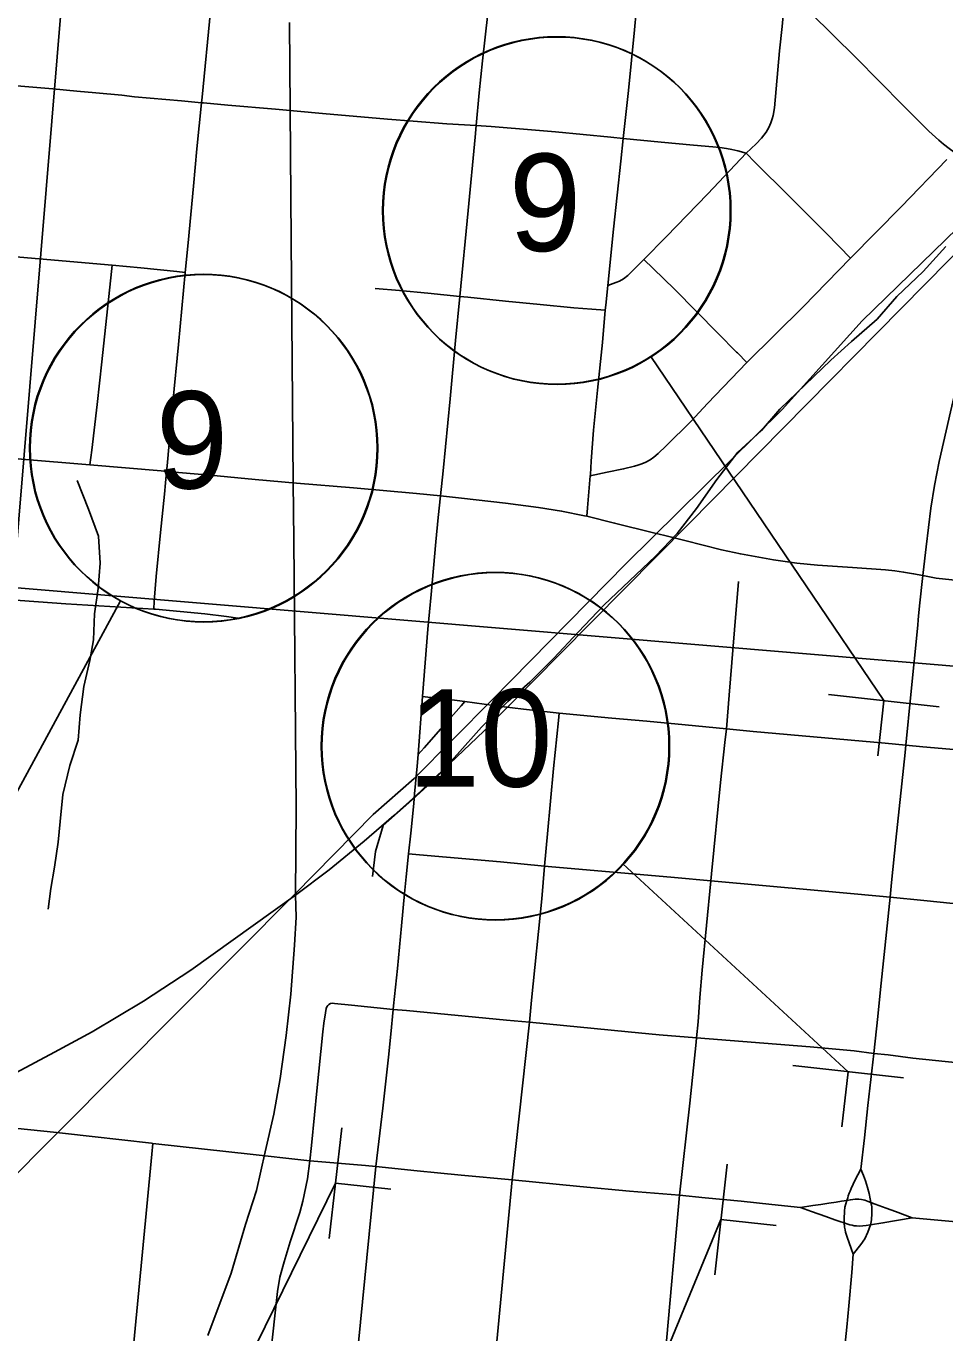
# Model space of a CAD drawing. Extents: x 0 to 1067, y 0 to 440.
# Drawn here: x 348.64 to 375.06, y 98.13 to 135.74 of the extents above; entities that cross this region are included whole.
import ezdxf

# ---------------------------------------------------------------- set-up
doc = ezdxf.new("R2010")
doc.units = 0
for name, color, linetype in [('Default', 7, 'Continuous'), ('GM_X_City_Street', 7, 'Continuous'), ('GM_X_Minor_River', 7, 'Continuous'), ('GM_X_Rail_Line', 7, 'Continuous'), ('GM_X_Section', 7, 'Continuous'), ('GM_X_State_Route', 7, 'Continuous'), ('GM_X_US_Route', 7, 'Continuous'), ('SH_Masking', 7, 'Continuous'), ('SH_Text', 7, 'Continuous'), ('SN_P_Signs', 7, 'Continuous')]:
    doc.layers.add(name, color=color, linetype=linetype)

msp = doc.modelspace()

# ---------------------------------------------------------------- linework, layer by layer
at = {"layer": 'Default'}
msp.add_line((358.398, 102.942), (356.8, 103.085), dxfattribs=at)
for points in [[(376.116, 128.559), (375.98, 127.967), (375.728, 126.841), (375.5, 125.823), (375.228, 124.636), (374.902, 123.209), (374.764, 122.519), (374.657, 121.861), (374.521, 120.755), (374.438, 120.015), (374.428, 119.923), (374.336, 119.054)], [(374.336, 119.054), (374.307, 118.759), (374.296, 118.648), (374.282, 118.501), (374.089, 116.5), (373.937, 115.042), (373.918, 114.831), (373.652, 112.312), (373.531, 111.088), (373.488, 110.667), (373.216, 108.012), (373.139, 107.235), (373.023, 106.172), (372.852, 104.672), (372.749, 103.747), (372.647, 102.84)], [(349.421, 103.902), (346.994, 104.157), (346.241, 104.236)], [(352.283, 103.581), (352.243, 103.585), (349.688, 103.874), (349.421, 103.902)], [(356.8, 103.085), (356.542, 103.11), (355.169, 103.261), (352.283, 103.581)], [(362.618, 102.534), (361.155, 102.668), (360.472, 102.733), (359.881, 102.788), (358.694, 102.915)], [(372.647, 102.84), (372.563, 102.676), (372.488, 102.534), (372.428, 102.408), (372.367, 102.28), (372.338, 102.211), (372.313, 102.146), (372.286, 102.069), (372.268, 102.013), (372.246, 101.937)], [(372.924, 101.242), (372.94, 101.325), (372.949, 101.39), (372.966, 101.555), (372.965, 101.679), (372.961, 101.751), (372.949, 101.817), (372.936, 101.882), (372.916, 101.986), (372.882, 102.138), (372.834, 102.316), (372.776, 102.507), (372.723, 102.658), (372.647, 102.84)], [(367.429, 102.089), (365.994, 102.212), (364.562, 102.339), (362.618, 102.534)], [(370.909, 101.738), (370.087, 101.824), (369.204, 101.916), (368.17, 102.019), (367.429, 102.089)], [(372.246, 101.937), (372.09, 101.916), (371.933, 101.894), (371.728, 101.863), (371.497, 101.826), (371.265, 101.791), (370.909, 101.738)], [(370.909, 101.738), (371.231, 101.619), (371.638, 101.479), (371.903, 101.383), (372.047, 101.335), (372.167, 101.296)], [(372.167, 101.296), (372.24, 101.267), (372.331, 101.24), (372.393, 101.225), (372.453, 101.213), (372.522, 101.206)], [(372.522, 101.206), (372.612, 101.204), (372.702, 101.21), (372.798, 101.222), (372.924, 101.242)]]:
    msp.add_lwpolyline(points, dxfattribs=at)
at = {"layer": 'GM_X_City_Street'}
for p, q in [((362.618, 102.534), (363.112, 107.076)), ((362.175, 97.883), (362.618, 102.534))]:
    msp.add_line(p, q, dxfattribs=at)
for points in [[(352.306, 118.96), (352.323, 119.189), (352.375, 119.899), (352.503, 121.16), (352.618, 122.271), (352.678, 122.924), (352.693, 123.087), (352.853, 124.905), (353.016, 126.572), (353.117, 127.608), (353.216, 128.647), (353.298, 129.499), (353.449, 131.13), (353.546, 132.206), (353.686, 133.531), (353.703, 133.689), (353.938, 136.172), (354.068, 137.506), (354.09, 137.748), (354.253, 139.547), (354.355, 140.548), (354.416, 141.332), (354.441, 141.657)], [(364.764, 121.631), (364.785, 121.875), (364.865, 122.791), (364.869, 122.831), (364.89, 123.218), (364.96, 124.109), (365.071, 125.258), (365.212, 126.629), (365.296, 127.562), (365.309, 127.705), (365.367, 128.272), (365.533, 129.889), (365.743, 131.849), (365.813, 132.503), (365.963, 133.886), (366.133, 135.626), (366.236, 136.674), (366.354, 137.865), (366.457, 138.781), (366.632, 140.525), (366.659, 140.791)], [(369.35, 132.081), (369.636, 132.347), (369.786, 132.513), (369.923, 132.69), (370, 132.818), (370.06, 132.954), (370.097, 133.068), (370.123, 133.167), (370.163, 133.387), (370.311, 135.022), (370.381, 135.727), (370.436, 136.263), (370.528, 137.175), (370.683, 138.884), (370.788, 140.109), (370.817, 140.452)], [(358.694, 102.915), (358.902, 104.593), (359.056, 106.065), (359.125, 106.727), (359.198, 107.44), (359.208, 107.542), (359.317, 108.619), (359.431, 109.844), (359.521, 110.77), (359.568, 111.252), (359.639, 111.913), (359.704, 112.512), (359.787, 113.366), (359.813, 113.642), (359.888, 114.443), (359.913, 114.772), (360.043, 116.447), (360.192, 118.381), (360.289, 119.379), (360.424, 120.896), (360.487, 121.6), (360.554, 122.217), (360.632, 122.935), (360.838, 125.014), (360.988, 126.685), (361.112, 127.956), (361.354, 130.432), (361.551, 132.545), (361.582, 132.878), (361.671, 133.819), (361.766, 134.739), (361.998, 136.788)], [(371.126, 136.188), (371.196, 136.121), (372.504, 134.831), (373.862, 133.451), (374.599, 132.716), (374.892, 132.451), (375.025, 132.34), (375.191, 132.212), (375.33, 132.111), (375.58, 131.985), (375.936, 131.818), (376.328, 131.671), (376.752, 131.513)], [(347.454, 134.094), (349.403, 133.93), (350.095, 133.865), (350.647, 133.819), (351.387, 133.747), (351.756, 133.706), (353.109, 133.584), (353.686, 133.531), (353.735, 133.526), (354.439, 133.46), (355.813, 133.349), (357.165, 133.221), (359.031, 133.058), (359.774, 132.998), (360.74, 132.929), (361.582, 132.878), (362.016, 132.851), (363.292, 132.741), (363.861, 132.692), (365.455, 132.538), (365.813, 132.503), (366.902, 132.4), (367.83, 132.312), (368.388, 132.264), (368.592, 132.241), (368.781, 132.212), (368.934, 132.183), (369.108, 132.146), (369.35, 132.081)], [(365.367, 128.272), (365.599, 128.359), (365.705, 128.401), (365.818, 128.465), (365.944, 128.561), (366.079, 128.69), (366.404, 129.021), (367.048, 129.676), (368.249, 130.906), (369.35, 132.081)], [(369.35, 132.081), (369.608, 131.811), (370.589, 130.842), (371.221, 130.211), (371.326, 130.106), (371.642, 129.791), (372.026, 129.391), (372.351, 129.062)], [(364.865, 122.791), (365.348, 122.896), (365.823, 122.993), (366.137, 123.073), (366.234, 123.104), (366.35, 123.144), (366.462, 123.186), (366.583, 123.256), (366.697, 123.331), (366.817, 123.433), (367.044, 123.654), (367.753, 124.356), (368.24, 124.881), (369.372, 126.058), (370.992, 127.658), (372.351, 129.062), (373.806, 130.536), (375.122, 131.902)], [(346.901, 129.218), (351.111, 128.853), (351.937, 128.782), (352.971, 128.672), (353.216, 128.647)], [(366.404, 129.021), (366.669, 128.765), (367.289, 128.169), (368.545, 126.892), (369.069, 126.357), (369.095, 126.33), (369.372, 126.058)], [(350.474, 123.111), (350.524, 123.534), (350.681, 124.845), (350.813, 126.072), (351.091, 128.672), (351.111, 128.853)], [(358.673, 128.187), (359.38, 128.124), (360.196, 128.048), (361.112, 127.956), (361.347, 127.932), (362.424, 127.825), (363.426, 127.721), (364.392, 127.63), (364.913, 127.591), (365.296, 127.562)], [(344.664, 123.625), (347.246, 123.396), (348.507, 123.277), (350.474, 123.111)], [(350.474, 123.111), (352.519, 122.938), (352.678, 122.924)], [(352.678, 122.924), (353.929, 122.812), (355.227, 122.691), (356.416, 122.585), (358.05, 122.45), (359.867, 122.289), (360.554, 122.217)], [(360.554, 122.217), (361.163, 122.153), (362.421, 122.012), (363.379, 121.886), (364.039, 121.779), (364.694, 121.648), (364.764, 121.631)], [(364.764, 121.631), (365.561, 121.435), (366.682, 121.158), (367.008, 121.077), (367.586, 120.932), (368.635, 120.667), (369.182, 120.548), (370.138, 120.381), (370.804, 120.284), (371.399, 120.222), (372.405, 120.154), (373.36, 120.09), (373.621, 120.065), (373.878, 120.026), (374.164, 119.976), (374.428, 119.923)], [(339.198, 120.018), (340.534, 119.899), (344.19, 119.569), (345.037, 119.494), (346.917, 119.328), (348.07, 119.234), (349.776, 119.115), (352.306, 118.96), (352.36, 118.957), (353.071, 118.894), (353.774, 118.823), (354.397, 118.748), (354.727, 118.699)], [(368.779, 115.515), (368.863, 116.482), (369.01, 118.358), (369.13, 119.752)], [(374.428, 119.923), (374.81, 119.853), (375.264, 119.799), (376.526, 119.675), (379.34, 119.399), (379.581, 119.368)], [(359.913, 114.772), (360.085, 114.967), (360.566, 115.513), (361.148, 116.176), (361.253, 116.296)], [(360.043, 116.447), (360.192, 116.429), (360.738, 116.366), (361.253, 116.296), (361.536, 116.259), (362.086, 116.184), (362.313, 116.153), (362.94, 116.077), (363.967, 115.963), (365.489, 115.818), (366.489, 115.734), (367.595, 115.628), (368.779, 115.515), (369.548, 115.441), (373.345, 115.101), (373.937, 115.042)], [(363.112, 107.076), (363.175, 107.703), (363.474, 110.62), (363.552, 111.561), (363.63, 112.496), (363.808, 114.37), (363.946, 115.749), (363.967, 115.963)], [(367.429, 102.089), (367.726, 104.742), (367.906, 106.493), (367.918, 106.617), (367.964, 107.082), (368.02, 107.785), (368.085, 108.564), (368.33, 111.143), (368.349, 111.34), (368.613, 113.968), (368.734, 115.12), (368.779, 115.515)], [(373.937, 115.042), (374.425, 114.997), (375.645, 114.889), (378.78, 114.612), (379.021, 114.591), (382.71, 114.268), (383.853, 114.166), (384.189, 114.124), (386.417, 113.917), (388.447, 113.728), (390.523, 113.524), (394.165, 113.168), (394.515, 113.136), (398.504, 112.778), (398.648, 112.765), (408.548, 111.817), (410.23, 111.667), (412.922, 111.384), (414.026, 111.268), (417.287, 110.919), (420.686, 110.598), (421.107, 110.558)], [(359.639, 111.913), (359.952, 111.886), (362.281, 111.687), (363.552, 111.561), (363.651, 111.551), (367.291, 111.239), (368.33, 111.143), (371.407, 110.857), (373.18, 110.695), (373.488, 110.667)], [(373.488, 110.667), (374.457, 110.569), (375.678, 110.446), (377.192, 110.311), (378.525, 110.185), (378.577, 110.18), (379.637, 110.085), (382.924, 109.793), (383.45, 109.743), (384.366, 109.656), (385.977, 109.501), (386.171, 109.475), (390.093, 109.102), (390.987, 109.016), (393.869, 108.743), (394.081, 108.724), (395.539, 108.593), (397.216, 108.45), (398.078, 108.377), (399.342, 108.265), (402.999, 107.914)], [(356.8, 103.085), (356.844, 103.524), (356.931, 104.407), (357.002, 105.095), (357.176, 106.789), (357.205, 107.041), (357.245, 107.343), (357.267, 107.464), (357.286, 107.514), (357.312, 107.555), (357.345, 107.584)], [(357.345, 107.584), (357.393, 107.606), (357.449, 107.614), (357.504, 107.61), (357.996, 107.558), (359.198, 107.44)], [(359.198, 107.44), (359.576, 107.403), (362.459, 107.13), (363.112, 107.076)], [(363.112, 107.076), (365.954, 106.794), (366.845, 106.707), (367.918, 106.617)], [(367.918, 106.617), (371.185, 106.358), (372.459, 106.251), (373.023, 106.172)], [(373.023, 106.172), (373.433, 106.128), (374.144, 106.037), (376.471, 105.8), (378.114, 105.635)], [(341.077, 85.173), (347.518, 91.121), (349.745, 93.08), (349.999, 93.346), (350.184, 93.574), (350.348, 93.817), (350.549, 94.171), (350.777, 94.637), (351.347, 96.011), (351.486, 96.432), (351.576, 96.791), (351.651, 97.19), (351.737, 97.854), (352.253, 103.274), (352.283, 103.581)], [(354.833, 88.561), (354.797, 88.851), (354.775, 89.023), (354.775, 89.152), (354.79, 89.3), (355.504, 95.991), (355.865, 99.321), (355.934, 99.736), (356.062, 100.17), (356.23, 100.752), (356.509, 101.598), (356.594, 101.922), (356.729, 102.563), (356.8, 103.085)], [(356.818, 83.639), (356.791, 83.69), (356.786, 83.779), (356.791, 83.892), (357.363, 89.368), (357.995, 95.811), (358.694, 102.915)], [(365.508, 82.695), (365.533, 82.923), (366.142, 88.583), (366.58, 92.902), (367.014, 97.469), (367.429, 102.089)]]:
    msp.add_lwpolyline(points, dxfattribs=at)
at = {"layer": 'GM_X_Minor_River'}
for points in [[(358.604, 111.259), (358.686, 111.987), (358.904, 112.735), (359.644, 113.384), (360.384, 114.055), (361.035, 114.773), (361.732, 115.558), (362.496, 116.297), (363.121, 116.856), (363.817, 117.551), (364.513, 118.291), (365.255, 119.076), (365.996, 119.77), (366.738, 120.486), (367.364, 121.136), (367.923, 121.856), (368.507, 122.689), (369.113, 123.476), (369.785, 124.103), (370.319, 124.709), (371.779, 126.12), (372.38, 126.656), (373.12, 127.305), (373.678, 127.956), (374.443, 128.672), (375.093, 129.39)], [(349.273, 110.324), (349.352, 110.915), (349.454, 111.528), (349.558, 112.256), (349.614, 112.847), (349.696, 113.621), (349.893, 114.46), (350.133, 115.185), (350.192, 115.913), (350.297, 116.732), (350.47, 117.481), (350.571, 118.072), (350.607, 118.823), (350.711, 119.55), (350.769, 120.278), (350.715, 121.054), (350.432, 121.833), (350.105, 122.659)]]:
    msp.add_lwpolyline(points, dxfattribs=at)
at = {"layer": 'GM_X_Rail_Line'}
for points in [[(353.862, 98.058), (354.532, 99.851), (354.947, 101.249), (355.26, 102.225), (355.509, 103.335), (355.758, 104.427), (355.943, 105.448), (356.115, 106.686), (356.249, 107.879), (356.358, 109.283), (356.402, 110.093), (356.384, 110.723), (356.404, 113.246), (356.341, 120.947), (356.322, 122.613), (356.264, 129.575), (356.216, 135.845)], [(348.344, 105.612), (349.451, 106.204), (350.534, 106.789), (352.017, 107.674), (353.373, 108.565), (356.384, 110.723), (357.351, 111.455), (358.357, 112.276), (359.217, 113.021), (359.847, 113.588), (361.8, 115.445), (363.987, 117.665), (367.695, 121.418), (376.531, 130.37), (377.357, 131.235), (377.909, 131.904), (378.756, 132.93)], [(356.37, 110.755), (358.619, 113.048), (359.795, 114.081), (362.038, 116.348), (365.9, 120.275), (370.388, 124.707), (372.687, 127.253), (375.425, 129.919), (376.58, 131.044)], [(356.37, 110.755), (341.091, 95.394), (330.427, 84.614)]]:
    msp.add_lwpolyline(points, dxfattribs=at)
at = {"layer": 'GM_X_Section'}
for points in [[(293.305, 184.745), (353.183, 178.942), (348.264, 119.585), (289.359, 125.481)], [(353.183, 178.942), (415.565, 173.729), (410.18, 114.397), (348.264, 119.585)], [(410.18, 114.397), (404.583, 52.958), (342.16, 58.91), (348.264, 119.585)]]:
    msp.add_lwpolyline(points, close=True, dxfattribs=at)
at = {"layer": 'GM_X_State_Route'}
for p, q in [((356.8, 103.085), (358.398, 102.942)), ((358.398, 102.942), (358.694, 102.915)), ((374.124, 101.438), (377.642, 101.116))]:
    msp.add_line(p, q, dxfattribs=at)
for points in [[(346.241, 104.236), (346.994, 104.157), (349.421, 103.902)], [(349.421, 103.902), (349.688, 103.874), (352.243, 103.585), (352.283, 103.581)], [(352.283, 103.581), (355.169, 103.261), (356.542, 103.11), (356.8, 103.085)], [(358.694, 102.915), (359.881, 102.788), (360.472, 102.733), (361.155, 102.668), (362.618, 102.534)], [(362.618, 102.534), (364.562, 102.339), (365.994, 102.212), (367.429, 102.089)], [(367.429, 102.089), (368.17, 102.019), (369.204, 101.916), (370.087, 101.824), (370.909, 101.738)], [(370.909, 101.738), (371.231, 101.619), (371.638, 101.479), (371.903, 101.383), (372.047, 101.335), (372.167, 101.296)], [(372.167, 101.296), (372.24, 101.267), (372.331, 101.24), (372.393, 101.225), (372.453, 101.213), (372.522, 101.206)], [(372.522, 101.206), (372.612, 101.204), (372.702, 101.21), (372.798, 101.222), (372.924, 101.242)], [(372.924, 101.242), (373.282, 101.292), (374.124, 101.438)]]:
    msp.add_lwpolyline(points, dxfattribs=at)
at = {"layer": 'GM_X_US_Route'}
for p, q in [((356.8, 103.085), (358.398, 102.942)), ((358.398, 102.942), (358.694, 102.915)), ((374.124, 101.438), (377.642, 101.116))]:
    msp.add_line(p, q, dxfattribs=at)
for points in [[(374.336, 119.054), (374.428, 119.923), (374.438, 120.015), (374.521, 120.755), (374.657, 121.861), (374.764, 122.519), (374.902, 123.209), (375.228, 124.636), (375.5, 125.823), (375.728, 126.841), (375.98, 127.967), (376.116, 128.559)], [(372.647, 102.84), (372.749, 103.747), (372.852, 104.672), (373.023, 106.172), (373.139, 107.235), (373.216, 108.012), (373.488, 110.667), (373.531, 111.088), (373.652, 112.312), (373.918, 114.831), (373.937, 115.042), (374.089, 116.5), (374.282, 118.501), (374.296, 118.648), (374.307, 118.759), (374.336, 119.054)], [(346.241, 104.236), (346.994, 104.157), (349.421, 103.902)], [(349.421, 103.902), (349.688, 103.874), (352.243, 103.585), (352.283, 103.581)], [(352.283, 103.581), (355.169, 103.261), (356.542, 103.11), (356.8, 103.085)], [(358.694, 102.915), (359.881, 102.788), (360.472, 102.733), (361.155, 102.668), (362.618, 102.534)], [(372.43, 100.391), (372.255, 100.882), (372.208, 101.031), (372.193, 101.098), (372.18, 101.169), (372.167, 101.296), (372.164, 101.415), (372.177, 101.628), (372.19, 101.743), (372.213, 101.84), (372.246, 101.937), (372.268, 102.013), (372.286, 102.069), (372.313, 102.146), (372.338, 102.211), (372.367, 102.28), (372.428, 102.408), (372.488, 102.534), (372.563, 102.676), (372.647, 102.84)], [(372.924, 101.242), (372.94, 101.325), (372.949, 101.39), (372.966, 101.555), (372.965, 101.679), (372.961, 101.751), (372.949, 101.817), (372.936, 101.882), (372.916, 101.986), (372.882, 102.138), (372.834, 102.316), (372.776, 102.507), (372.723, 102.658), (372.647, 102.84)], [(362.618, 102.534), (364.562, 102.339), (365.994, 102.212), (367.429, 102.089)], [(367.429, 102.089), (368.17, 102.019), (369.204, 101.916), (370.087, 101.824), (370.909, 101.738)], [(370.909, 101.738), (371.265, 101.791), (371.497, 101.826), (371.728, 101.863), (371.933, 101.894), (372.09, 101.916), (372.246, 101.937), (372.347, 101.959), (372.418, 101.971), (372.484, 101.979), (372.589, 101.98), (372.663, 101.971), (372.761, 101.952), (372.861, 101.915), (372.936, 101.882), (373.057, 101.838), (373.379, 101.72), (373.642, 101.623), (374.124, 101.438)], [(370.909, 101.738), (371.231, 101.619), (371.638, 101.479), (371.903, 101.383), (372.047, 101.335), (372.167, 101.296)], [(372.167, 101.296), (372.24, 101.267), (372.331, 101.24), (372.393, 101.225), (372.453, 101.213), (372.522, 101.206)], [(372.43, 100.391), (372.649, 100.674), (372.761, 100.839), (372.849, 101.024), (372.924, 101.242)], [(372.522, 101.206), (372.612, 101.204), (372.702, 101.21), (372.798, 101.222), (372.924, 101.242)], [(372.924, 101.242), (373.282, 101.292), (374.124, 101.438)], [(371.638, 92.486), (371.674, 92.844), (371.823, 94.223), (372.017, 96.104), (372.111, 97.004), (372.241, 98.289), (372.3, 98.905), (372.391, 99.863), (372.43, 100.391)]]:
    msp.add_lwpolyline(points, dxfattribs=at)
at = {"layer": 'SH_Masking'}
for centre in [(363.911, 130.424), (353.753, 123.588), (362.147, 115.008)]:
    msp.add_circle(centre, 5, dxfattribs=at)
at = {"layer": 'SH_Text'}
for p, q in [((373.304, 116.327), (366.606, 126.232)), ((343.906, 105.458), (351.352, 119.2)), ((372.278, 105.646), (365.805, 111.628)), ((352.929, 93.034), (357.536, 102.44)), ((364.089, 90.413), (368.622, 101.394))]:
    msp.add_line(p, q, dxfattribs=at)
for centre in [(363.892, 130.432), (353.734, 123.596), (362.128, 115.016)]:
    msp.add_circle(centre, 5, dxfattribs=at)
at = {"layer": 'SN_P_Signs'}
for p, q in [((374.898, 116.149), (371.717, 116.498)), ((373.307, 116.323), (373.133, 114.733)), ((373.869, 105.471), (370.688, 105.82)), ((372.278, 105.646), (372.104, 104.055)), ((357.357, 100.85), (357.716, 104.03)), ((368.443, 99.804), (368.802, 102.984)), ((357.536, 102.44), (359.126, 102.261)), ((368.622, 101.394), (370.212, 101.215))]:
    msp.add_line(p, q, dxfattribs=at)

# ---------------------------------------------------------------- texts
at = {"layer": 'SH_Text'}
for s, p in [('9', (362.524, 129.264)), ('9', (352.366, 122.429)), ('10', (359.615, 113.849))]:
    msp.add_text(s, height=2.8, rotation=360, dxfattribs=at).set_placement(p)

doc.saveas('drawing.dxf')
